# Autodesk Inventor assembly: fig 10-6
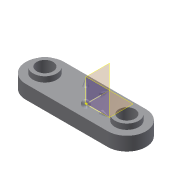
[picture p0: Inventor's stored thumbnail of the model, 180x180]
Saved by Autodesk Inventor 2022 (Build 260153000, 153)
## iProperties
Created: 2010-08
Part Number: fig 10-6
Document SubType Name: Assembly
Designer: CADSoft
Author: CADSoft
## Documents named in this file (2)
- D:\PROJECTS_2021\Resources\Part Files\c10_Inv_2021_prt\fig 10-6.iam
- D:\PROJECTS_2021\Resources\Part Files\c10_Inv_2021_prt\Part6.ipt
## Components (1 placed, 1 different names)
1. Part6:1
